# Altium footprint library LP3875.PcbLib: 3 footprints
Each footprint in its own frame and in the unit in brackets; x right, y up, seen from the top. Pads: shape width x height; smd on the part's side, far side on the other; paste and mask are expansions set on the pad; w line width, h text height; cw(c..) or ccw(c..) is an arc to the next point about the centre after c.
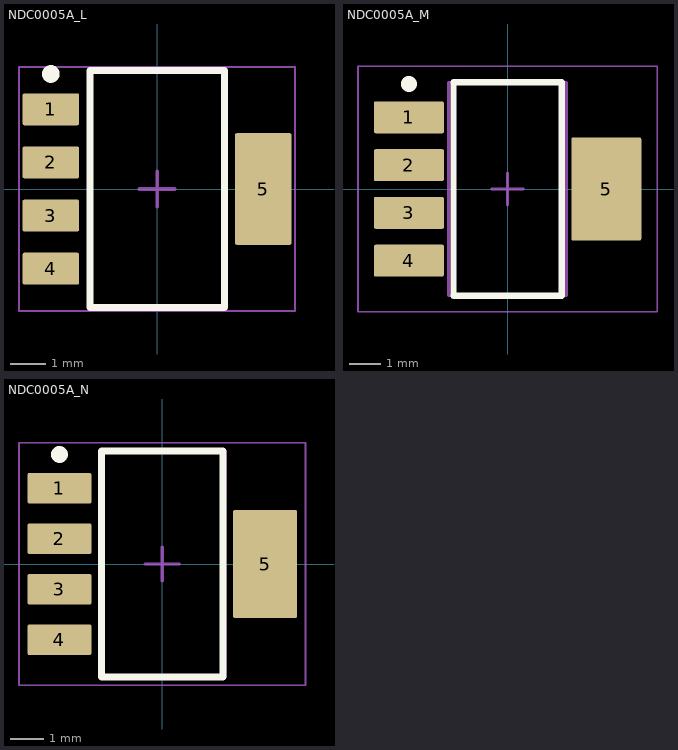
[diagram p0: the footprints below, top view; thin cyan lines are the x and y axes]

## NDC0005A_L [mm] "SOT223, 5-Leads, Body 6.7x3.71mm, Pitch 1.5mm, IPC High Density"
height 1.8
pads (5):
  rrect11% 1.6x0.9 smd: 1(-3,2.25) 2(-3,0.75) 3(-3,-0.75) 4(-3,-2.25)
  rrect6% 1.6x3.15 smd: 5(3,0)
Top Overlay:
  circle w0.25: c-3,3.25 r0.125
  lines w0.2: -1.9,-3.35 -1.9,3.35 1.9,3.35 1.9,-3.35 -1.9,-3.35
Mechanical 1:
  text ".Designator" at -1.651,-0.381 h0.9
Mechanical 13:
  lines w0.1: -1.855,-3.35 -1.855,3.35 1.855,3.35 1.855,-3.35 -1.855,-3.35
Mechanical 15:
  lines w0.05: -3.9,-3.45 -3.9,3.45 3.9,3.45 3.9,-3.45 -3.9,-3.45
  lines w0.1: -0.5,0 0.5,0 ; 0,-0.5 0,0.5
3D body "NDC0005A.stp": height 1.7, standoff 0.02, extent -3.482,-3.25 3.482,3.25

## NDC0005A_M [mm] "SOT223, 5-Leads, Body 6.7x3.71mm, Pitch 1.5mm, IPC Low Density"
height 1.8
pads (5):
  rrect10% 2.2x1 smd: 1(-3.1,2.25) 2(-3.1,0.75) 3(-3.1,-0.75) 4(-3.1,-2.25)
  rrect5% 2.2x3.25 smd: 5(3.1,0)
Top Overlay:
  circle w0.25: c-3.1,3.3 r0.125
  lines w0.2: -1.7,-3.35 1.7,-3.35 1.7,3.35 -1.7,3.35 -1.7,-3.35
Mechanical 1:
  text ".Designator" at -1.524,-0.381 h0.8
Mechanical 13:
  lines w0.1: -1.855,-3.35 1.855,-3.35 1.855,3.35 -1.855,3.35 -1.855,-3.35
Mechanical 15:
  lines w0.05: -4.7,-3.85 4.7,-3.85 4.7,3.85 -4.7,3.85 -4.7,-3.85
  lines w0.1: -0.5,0 0.5,0 ; 0,-0.5 0,0.5
3D body "NDC0005A.stp": height 1.7, standoff 0.02, extent -3.482,-3.25 3.482,3.25

## NDC0005A_N [mm] "SOT223, 5-Leads, Body 6.7x3.71mm, Pitch 1.5mm, IPC Medium Density"
height 1.8
pads (5):
  rrect11% 1.9x0.9 smd: 1(-3.05,2.25) 2(-3.05,0.75) 3(-3.05,-0.75) 4(-3.05,-2.25)
  rrect5% 1.9x3.2 smd: 5(3.05,0)
Top Overlay:
  circle w0.25: c-3.05,3.25 r0.125
  lines w0.2: -1.8,-3.35 1.8,-3.35 1.8,3.35 -1.8,3.35 -1.8,-3.35
Mechanical 1:
  text ".Designator" at -1.524,-0.381 h0.8
Mechanical 13:
  lines w0.1: -1.855,-3.35 1.855,-3.35 1.855,3.35 -1.855,3.35 -1.855,-3.35
Mechanical 15:
  lines w0.05: -4.25,-3.6 4.25,-3.6 4.25,3.6 -4.25,3.6 -4.25,-3.6
  lines w0.1: -0.5,0 0.5,0 ; 0,-0.5 0,0.5
3D body "NDC0005A.stp": height 1.7, standoff 0.02, extent -3.482,-3.25 3.482,3.25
